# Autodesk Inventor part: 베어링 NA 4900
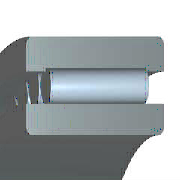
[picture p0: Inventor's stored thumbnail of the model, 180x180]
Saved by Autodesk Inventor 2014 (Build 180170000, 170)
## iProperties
Created: 2009-02
Part Number: 베어링 NA 4900
Material: Steel, Mild
Description: 니들 롤러 베어링 - 경계 치수 및 공차
Document SubType Name: Modeling
Standard: KS B 2029
Designer: SeoGD™
Standards Organization: KS
Language: ko-KR
Size Designation: NA 4900 - 10 x 22 x 13
Categories: <MemberInstance><Categories><Category DisplayName="샤프트 부품" InternalName="7f7aeb1f-a693-4053-b835-cee3144e0d98" Mnemonic="SHFT"><Category DisplayName="베어링" Inter
Density: 7.86 g/cm^3
Mass: 23.8213 g
Surface Area: 38.613 cm^2
Volume: 3.0307 cm^3
Appearance: Metal-Steel
IsCustomPart: 0
Author: SeoGD™
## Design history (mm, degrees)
sketch "스케치"
  geometry: L1 (1.857, 9)-(11.143, 9); L2 (11.143, 9)-(11.143, 7); L3 (13, 7)-(0, 7); L4 (1.857, 7)-(1.857, 9); L5 (1.857, 8)-(11.143, 8); L6 (6.5, 8)-(6.5, 7); L7 (0, 5)-(13, 5); L8 (0, 11)-(13, 11); L9 (13, 5)-(13, 7); L10 (13, 8.8)-(13, 11); L11 (1.857, 8.8)-(0, 8.8); L12 (11.143, 8.8)-(13, 8.8); L13 (-6, 0)-(36, 0) reference; L14 (0, -1.9)-(0, 14.9) reference
  constraints: 24 end point, 8 point on line, 3 midpoint, 3 parallel, 3 perpendicular, 2 symmetric about line, 1 horizontal, 1 other
  dimensions: "d6" = 10 diameter of L7 L13 (= WD); "d7" = 14 diameter of L3 L13 (= KID1); "d8" = 22 diameter of L8 L13 (= BD); "d9" = 16 diameter of L6.start L13 (= 0.5 x WD + 0.5 x BD); "d10" = 17.6 diameter of L12 L13 (= 0.9 x BD + 0.9 x WD - 0.8 x KID1); "d11" = 18 diameter of L1 L13 (= BD + WD - KID1); "d12" = 1.85714 distance between parallel lines of L14 L4 (= 0.142857 x KB); "d13" = 13 distance between parallel lines of L14 L9 (= KB); "d14" = 11.14286 distance between parallel lines of L14 L2 (= 0.857143 x KB)
revolve "본체" stored, may be unused: angle "d17" = 90 deg
revolve "롤러" stored, may be unused: angle "d18" = 90 deg
pattern_circular "IDS_ARRAYROLLER[SIMPL:T]" dims angle "d2" = 360 deg
body "Solid1"
fillet "모깎기1" dims "d0" = 0.3 (= KRS)
other parameters: "WD" = 10 [user parameter; used in 6 equation terms], "BD" = 22 [user parameter; used in 6 equation terms], "KB" = 13 [user parameter; used in 3 equation terms], "KID1" = 14 [user parameter; used in 4 equation terms], "KRS" = 0.3 [user parameter; used in 1 equation term], "d3" = 0, "d4" = 0, "d5" = 0, "d15" = 0, "d16" = 0, "BC0" = 9150000 [user parameter], "WR" = 5 (= 0.5 x WD) [user parameter], "BBA" = 0 [user parameter], "BC" = 8150000 [user parameter], "BR" = 11 (= 0.5 x BD) [user parameter]
